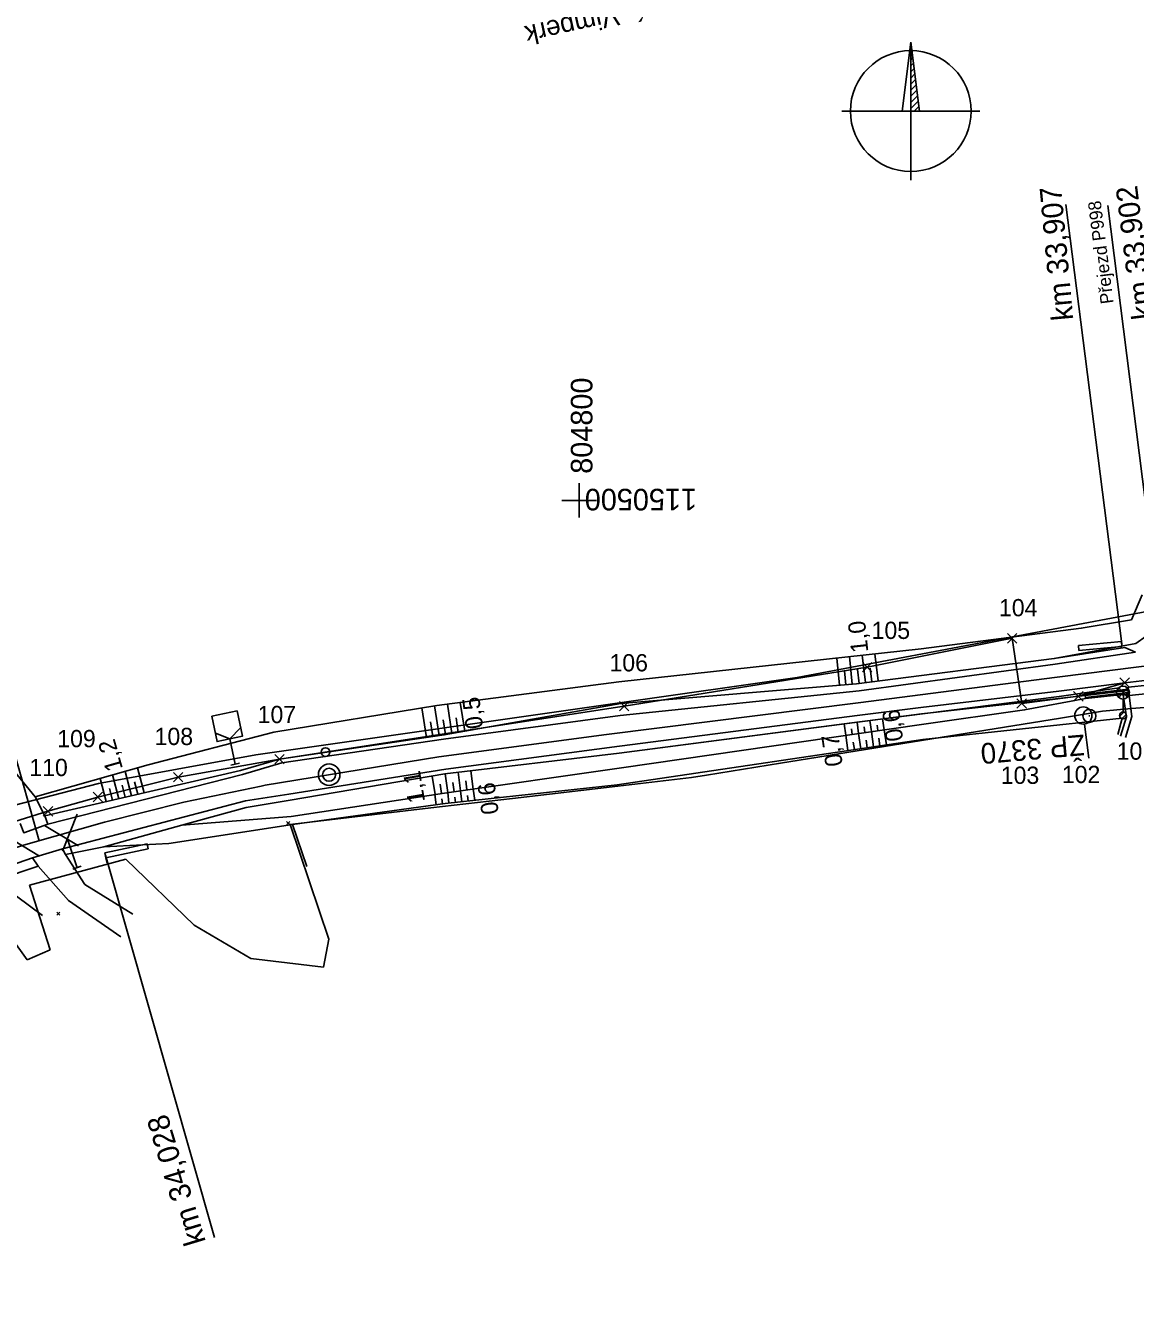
# Model space of a CAD drawing. Extents: x -805730 to -804640, y -1150889 to -1150366.
# Drawn here: x -804864.2 to -804735.5, y -1150592.5 to -1150444.9 of the extents above; entities that cross this region are included whole.
import ezdxf

# ---------------------------------------------------------------- set-up
doc = ezdxf.new("R2010")
doc.units = 0
for name, color, linetype in [('0381KM032-037P - Vrstva 1', 7, 'Continuous'), ('0381KM032-037P - Vrstva 13', 7, 'Continuous'), ('0381KM032-037P - Vrstva 17', 7, 'Continuous'), ('0381KM032-037P - Vrstva 25', 7, 'Continuous'), ('0381KM032-037P - Vrstva 36', 7, 'Continuous'), ('0381KM032-037P - Vrstva 4', 7, 'Continuous'), ('0381KM032-037P - Vrstva 43', 7, 'Continuous'), ('0381KM032-037P - Vrstva 48', 7, 'Continuous'), ('0381KM032-037P - Vrstva 49', 7, 'Continuous'), ('0381KM032-037P - Vrstva 51', 7, 'Continuous'), ('0381KM032-037P - Vrstva 7', 7, 'Continuous'), ('0381KM032-037P - Vrstva 9', 7, 'Continuous'), ('Default', 7, 'Continuous'), ('formát', 7, 'Continuous'), ('hran DP - hran DP', 7, 'Continuous'), ('krizky_1000 - souradnice', 7, 'Continuous'), ('krizky_1000 - Vrstva 1', 7, 'Continuous'), ('legenda - Vrstva 7', 7, 'Continuous'), ('PSR_C2_2_Lomove_body_Vimperk - Vrstva 60', 7, 'Continuous'), ('PSR_C2_2_trasa_Vimperk - Kabelová trasa', 7, 'Continuous'), ('vyt_sit - stávající', 7, 'Continuous')]:
    doc.layers.add(name, color=color, linetype=linetype)

msp = doc.modelspace()

# ---------------------------------------------------------------- linework, layer by layer
at = {"layer": '0381KM032-037P - Vrstva 1'}
for points in [[(-804673.35, -1150511.49), (-804675.7, -1150511.78), (-804698.85, -1150514.71), (-804701.61, -1150515.06), (-804722.18, -1150517.67), (-804729.05, -1150518.54), (-804735.1, -1150519.31), (-804744.56, -1150520.5), (-804767.65, -1150523.46), (-804791, -1150526.42)], [(-804791, -1150526.42), (-804796.82, -1150527.16), (-804816.26, -1150529.72), (-804836.43, -1150533.03), (-804836.89, -1150533.13)], [(-804836.89, -1150533.13), (-804845.84, -1150535.01), (-804855.06, -1150537.3), (-804860.78, -1150538.93), (-804864.46, -1150539.98), (-804872.35, -1150542.54)]]:
    msp.add_lwpolyline(points, dxfattribs=at)
at = {"layer": '0381KM032-037P - Vrstva 13'}
msp.add_line((-804736.93, -1150522.56), (-804736.22, -1150522.62), dxfattribs=at)
for points in [[(-804736.32, -1150521.88), (-804741.33, -1150522.48), (-804741.32, -1150522.62), (-804736.39, -1150522.04)], [(-804736.33, -1150522.27), (-804741.29, -1150522.87), (-804741.32, -1150522.62)], [(-804741.29, -1150522.87), (-804741.28, -1150522.98), (-804736.24, -1150522.43)], [(-804736.93, -1150522.56), (-804736.54, -1150525.1), (-804737.22, -1150527.34)], [(-804736.32, -1150521.88), (-804736.39, -1150522.04), (-804736.33, -1150522.27), (-804736.24, -1150522.43)], [(-804736.22, -1150522.62), (-804735.92, -1150525.05), (-804736.64, -1150527.49)]]:
    msp.add_lwpolyline(points, dxfattribs=at)
at = {"layer": '0381KM032-037P - Vrstva 17'}
msp.add_line((-804831.6, -1150542.45), (-804833.23, -1150537.58), dxfattribs=at)
for points in [[(-804734.71, -1150510.96), (-804735.96, -1150513.84), (-804741.77, -1150514.83), (-804760.36, -1150517.2), (-804795.4, -1150521.06), (-804816.51, -1150523.78), (-804835.4, -1150526.88), (-804850, -1150530.66), (-804863.08, -1150534.36), (-804866.23, -1150530.55), (-804868.05, -1150528.28)], [(-804833.23, -1150537.58), (-804815.54, -1150535.16), (-804795.6, -1150532.98), (-804760.14, -1150527.72), (-804737.02, -1150525.24), (-804737.52, -1150527.15)]]:
    msp.add_lwpolyline(points, dxfattribs=at)
at = {"layer": '0381KM032-037P - Vrstva 25'}
for p, q in [((-804737.43, -1150521.73), (-804736.43, -1150522.84)), ((-804737.41, -1150522.86), (-804736.43, -1150521.74)), ((-804736.93, -1150523.04), (-804736.93, -1150524.54)), ((-804737.32, -1150525.02), (-804736.85, -1150524.55)), ((-804737.06, -1150525.32), (-804736.56, -1150524.82))]:
    msp.add_line(p, q, dxfattribs=at)
for centre, radius in [((-804736.94, -1150522.29), 0.749), ((-804736.93, -1150524.94), 0.4), ((-804736.93, -1150524.94), 0.4)]:
    msp.add_circle(centre, radius, dxfattribs=at)
at = {"layer": '0381KM032-037P - Vrstva 36'}
for p, q in [((-804741.54, -1150524.95), (-804741.54, -1150524.95)), ((-804741.41, -1150525.95), (-804740.91, -1150529.91))]:
    msp.add_line(p, q, dxfattribs=at)
msp.add_circle((-804741.54, -1150524.95), 1, dxfattribs=at)
at = {"layer": '0381KM032-037P - Vrstva 4'}
for p, q in [((-804738.68, -1150465.82), (-804731.99, -1150518.9)), ((-804874.8, -1150496.75), (-804862.62, -1150539.46)), ((-804859.94, -1150540.68), (-804858.22, -1150536.4)), ((-804862.01, -1150537.68), (-804858.05, -1150540.04)), ((-804862.58, -1150541.24), (-804866.52, -1150538.84)), ((-804858.24, -1150542.59), (-804859.36, -1150539.27)), ((-804854.94, -1150541.15), (-804854.94, -1150541.15)), ((-804858.72, -1150542.75), (-804857.77, -1150542.43))]:
    msp.add_line(p, q, dxfattribs=at)
for points in [[(-804735.49, -1150517.59), (-804736.73, -1150517.05), (-804744.9, -1150518.34), (-804767.83, -1150521.26)], [(-804735.49, -1150517.59), (-804744.82, -1150519), (-804767.55, -1150522.1)], [(-804767.83, -1150521.26), (-804795.17, -1150523.55), (-804815.65, -1150527.19), (-804834.76, -1150530), (-804839.27, -1150531.31), (-804861.98, -1150536.58), (-804861.64, -1150537.54)], [(-804767.55, -1150522.1), (-804795.24, -1150524.96), (-804815.73, -1150527.69), (-804834.48, -1150530.44), (-804839.03, -1150531.78), (-804861.64, -1150537.54)], [(-804736.74, -1150521.15), (-804737.38, -1150521.73), (-804744.34, -1150522.73), (-804767.48, -1150525.67)], [(-804736.74, -1150521.15), (-804744.39, -1150522.13), (-804760.4, -1150524), (-804767.46, -1150524.91)], [(-804767.46, -1150524.91), (-804795.31, -1150528.51), (-804815.46, -1150531.15), (-804833.67, -1150534.06), (-804838.71, -1150534.85), (-804859.92, -1150540.42), (-804859.57, -1150541.07)], [(-804767.48, -1150525.67), (-804795.35, -1150529.3), (-804815.58, -1150531.71), (-804833.51, -1150534.75), (-804838.64, -1150535.6), (-804846.07, -1150537.67)], [(-804859.57, -1150541.07), (-804855.14, -1150540.16), (-804846.07, -1150537.67)], [(-804862.73, -1150542.41), (-804863.39, -1150541.46), (-804892.29, -1150551.48), (-804910.22, -1150558.86), (-804951.61, -1150576.23), (-804993.7, -1150593.96), (-805038.63, -1150612.92), (-805049.62, -1150617.53), (-805055.59, -1150619.94), (-805066.74, -1150624.75), (-805096.44, -1150637.01)], [(-804864.94, -1150543.15), (-804862.73, -1150542.41), (-804862.73, -1150542.41)]]:
    msp.add_lwpolyline(points, dxfattribs=at)
at = {"layer": '0381KM032-037P - Vrstva 43'}
msp.add_lwpolyline([(-804736.33, -1150521.65), (-804729.5, -1150520.98), (-804729.45, -1150521.92), (-804736.22, -1150522.62)], close=True, dxfattribs=at)
at = {"layer": '0381KM032-037P - Vrstva 48'}
for p, q in [((-804768.33, -1150521.3), (-804768.64, -1150518.12)), ((-804766.81, -1150521.13), (-804767.19, -1150517.96)), ((-804765.32, -1150520.94), (-804765.7, -1150517.79)), ((-804769.83, -1150521.43), (-804770.13, -1150518.28)), ((-804767.55, -1150521.23), (-804767.74, -1150519.63)), ((-804766.07, -1150521.04), (-804766.25, -1150519.46)), ((-804769.08, -1150521.37), (-804769.23, -1150519.78)), ((-804817.72, -1150527.49), (-804818.25, -1150524.06)), ((-804816.23, -1150527.27), (-804816.77, -1150523.82)), ((-804814.76, -1150527.03), (-804815.28, -1150523.62)), ((-804813.28, -1150526.77), (-804813.79, -1150523.43)), ((-804815.5, -1150527.16), (-804815.76, -1150525.44)), ((-804814.02, -1150526.9), (-804814.28, -1150525.21)), ((-804766.12, -1150526.81), (-804766.3, -1150525.53)), ((-804764.64, -1150526.59), (-804764.81, -1150525.34)), ((-804816.97, -1150527.38), (-804817.24, -1150525.66)), ((-804769.09, -1150527.24), (-804769.27, -1150525.92)), ((-804768.35, -1150527.13), (-804768.44, -1150526.48)), ((-804767.6, -1150527.03), (-804767.78, -1150525.73)), ((-804766.86, -1150526.92), (-804766.95, -1150526.27)), ((-804765.87, -1150528.57), (-804766.12, -1150526.81)), ((-804765.38, -1150526.7), (-804765.46, -1150526.07)), ((-804764.38, -1150528.35), (-804764.64, -1150526.59)), ((-804768.83, -1150529.01), (-804769.09, -1150527.24)), ((-804768.09, -1150528.9), (-804768.22, -1150528.02)), ((-804767.35, -1150528.79), (-804767.61, -1150527.03)), ((-804766.61, -1150528.68), (-804766.74, -1150527.8)), ((-804765.12, -1150528.46), (-804765.25, -1150527.58)), ((-804851.93, -1150534.25), (-804852.66, -1150531.42)), ((-804850.47, -1150533.91), (-804851.22, -1150531.01)), ((-804812.28, -1150533.47), (-804812.56, -1150531.35)), ((-804854.85, -1150534.93), (-804855.55, -1150532.23)), ((-804853.39, -1150534.59), (-804854.11, -1150531.82)), ((-804851.2, -1150534.08), (-804851.57, -1150532.65)), ((-804816.7, -1150534.11), (-804817.05, -1150531.96)), ((-804815.96, -1150534), (-804816.14, -1150532.92)), ((-804815.25, -1150533.89), (-804815.54, -1150531.71)), ((-804814.51, -1150533.79), (-804814.65, -1150532.7)), ((-804813.77, -1150533.68), (-804814.05, -1150531.53)), ((-804813.02, -1150533.57), (-804813.16, -1150532.51)), ((-804854.12, -1150534.76), (-804854.48, -1150533.4)), ((-804852.66, -1150534.42), (-804853.02, -1150533.02)), ((-804816.58, -1150535.3), (-804816.73, -1150534.11)), ((-804815.1, -1150535.11), (-804815.25, -1150533.89)), ((-804813.6, -1150534.95), (-804813.76, -1150533.68)), ((-804812.86, -1150534.87), (-804812.94, -1150534.22)), ((-804812.11, -1150534.78), (-804812.28, -1150533.47)), ((-804815.84, -1150535.2), (-804815.92, -1150534.6)), ((-804814.35, -1150535.03), (-804814.43, -1150534.41))]:
    msp.add_line(p, q, dxfattribs=at)
at = {"layer": '0381KM032-037P - Vrstva 49'}
for p, q in [((-804861.98, -1150536.58), (-804863.08, -1150534.36)), ((-804833.93, -1150537.24), (-804833.57, -1150537.6)), ((-804833.57, -1150537.24), (-804833.92, -1150537.6)), ((-804855.14, -1150540.16), (-804859.57, -1150541.07)), ((-804860.23, -1150547.75), (-804860.58, -1150548.11)), ((-804860.58, -1150547.76), (-804860.23, -1150548.11))]:
    msp.add_line(p, q, dxfattribs=at)
for points in [[(-804731.33, -1150510.42), (-804733.06, -1150514.89), (-804735.43, -1150516.61), (-804744.9, -1150518.34), (-804767.83, -1150521.26), (-804795.17, -1150523.55), (-804815.65, -1150527.19), (-804834.76, -1150530), (-804839.27, -1150531.31), (-804861.98, -1150536.58)], [(-804735.96, -1150513.84), (-804741.77, -1150514.83), (-804760.36, -1150517.2), (-804795.4, -1150521.06), (-804816.51, -1150523.78), (-804835.4, -1150526.88), (-804850, -1150530.66), (-804863.08, -1150534.36)], [(-804741.32, -1150522.62), (-804760.31, -1150524.76), (-804795.35, -1150529.3), (-804815.58, -1150531.71), (-804833.51, -1150534.75), (-804838.64, -1150535.6), (-804846.07, -1150537.67)], [(-804846.07, -1150537.67), (-804833.4, -1150536.66), (-804815.63, -1150533.95), (-804795.08, -1150531.02), (-804760.31, -1150525.97), (-804748.35, -1150524.3), (-804741.28, -1150522.98)], [(-804741.32, -1150522.62), (-804741.29, -1150522.87), (-804741.28, -1150522.98)], [(-804737.02, -1150525.24), (-804760.14, -1150527.72), (-804795.6, -1150532.98), (-804815.54, -1150535.16), (-804833.23, -1150537.58)], [(-804833.23, -1150537.58), (-804847.59, -1150539.77), (-804855.14, -1150540.16)], [(-804859.57, -1150541.07), (-804857.34, -1150544.52), (-804851.77, -1150547.99)], [(-804869.27, -1150544.65), (-804865.03, -1150543.19), (-804864.94, -1150543.15), (-804862.73, -1150542.41)], [(-804862.73, -1150542.41), (-804859.23, -1150546.38), (-804853.15, -1150550.59)], [(-804865.78, -1150545.2), (-804865.26, -1150545.89), (-804862.25, -1150548.13)]]:
    msp.add_lwpolyline(points, dxfattribs=at)
at = {"layer": '0381KM032-037P - Vrstva 51'}
msp.add_line((-804861.98, -1150536.58), (-804863.08, -1150534.36), dxfattribs=at)
for points in [[(-804736.22, -1150522.62), (-804735.92, -1150525.05), (-804736.64, -1150527.49)], [(-804861.98, -1150536.58), (-804861.64, -1150537.54), (-804864.42, -1150538.53), (-804864.84, -1150537.45)], [(-804859.57, -1150541.07), (-804859.92, -1150540.42), (-804863.39, -1150541.46), (-804862.73, -1150542.41)], [(-804859.57, -1150541.07), (-804857.34, -1150544.52), (-804851.77, -1150547.99)], [(-804853.15, -1150550.59), (-804859.23, -1150546.38), (-804862.73, -1150542.41)]]:
    msp.add_lwpolyline(points, dxfattribs=at)
at = {"layer": '0381KM032-037P - Vrstva 7'}
for p, q in [((-804840.52, -1150527.66), (-804839.9, -1150530.59)), ((-804829.48, -1150529.18), (-804829.38, -1150529.18)), ((-804840.39, -1150530.7), (-804839.41, -1150530.49))]:
    msp.add_line(p, q, dxfattribs=at)
for points in [[(-804840.52, -1150527.66), (-804839.05, -1150527.35), (-804839.67, -1150524.41), (-804842.6, -1150525.03), (-804841.99, -1150527.97), (-804840.52, -1150527.66)], [(-804842.19, -1150526.99), (-804840.52, -1150527.66), (-804839.26, -1150526.37)]]:
    msp.add_lwpolyline(points, dxfattribs=at)
for centre, radius in [((-804829.43, -1150529.18), 0.5), ((-804829, -1150531.81), 1.25), ((-804829, -1150531.81), 0.752)]:
    msp.add_circle(centre, radius, dxfattribs=at)
at = {"layer": '0381KM032-037P - Vrstva 9'}
for p, q in [((-804737.08, -1150516.65), (-804743.56, -1150465.71)), ((-804737.11, -1150516.35), (-804742.09, -1150516.81)), ((-804737.11, -1150516.35), (-804737.17, -1150515.76)), ((-804737.06, -1150516.95), (-804737.11, -1150516.35)), ((-804742.09, -1150516.81), (-804742.04, -1150517.41)), ((-804742.04, -1150517.41), (-804737.06, -1150516.95)), ((-804850.11, -1150539.83), (-804855, -1150540.85)), ((-804849.98, -1150540.42), (-804850.11, -1150539.83)), ((-804855, -1150540.85), (-804854.88, -1150541.44)), ((-804854.94, -1150541.15), (-804842.3, -1150585.48)), ((-804854.88, -1150541.44), (-804849.98, -1150540.42)), ((-804854.88, -1150541.44), (-804854.75, -1150542.03))]:
    msp.add_line(p, q, dxfattribs=at)
at = {"layer": 'formát'}
for p, q in [((-804761.55, -1150446.86), (-804761.55, -1150462.86)), ((-804761.55, -1150447.49), (-804761.48, -1150447.42)), ((-804761.55, -1150448.2), (-804761.41, -1150448.05)), ((-804761.55, -1150448.91), (-804761.33, -1150448.68)), ((-804761.55, -1150449.61), (-804761.25, -1150449.31)), ((-804761.55, -1150450.32), (-804761.17, -1150449.94)), ((-804761.55, -1150451.03), (-804761.09, -1150450.56)), ((-804761.55, -1150451.74), (-804761.01, -1150451.19)), ((-804761.55, -1150452.44), (-804760.93, -1150451.82)), ((-804761.55, -1150453.15), (-804760.86, -1150452.45)), ((-804761.55, -1150453.86), (-804760.78, -1150453.08)), ((-804761.55, -1150454.56), (-804760.7, -1150453.71)), ((-804761.14, -1150454.86), (-804760.62, -1150454.34)), ((-804769.55, -1150454.86), (-804753.55, -1150454.86))]:
    msp.add_line(p, q, dxfattribs=at)
for points in [[(-804761.55, -1150446.86), (-804762.55, -1150454.86)], [(-804761.55, -1150446.86), (-804760.55, -1150454.86)], [(-804761.55, -1150446.86), (-804761.55, -1150454.86), (-804760.55, -1150454.86), (-804761.55, -1150446.86)]]:
    msp.add_lwpolyline(points, dxfattribs=at)
msp.add_circle((-804761.55, -1150454.86), 7, dxfattribs=at)
at = {"layer": 'hran DP - hran DP'}
for p, q in [((-804747.72, -1150515.43), (-804723.03, -1150510.78)), ((-804774.72, -1150520.52), (-804747.72, -1150515.43)), ((-804795.05, -1150523.42), (-804774.72, -1150520.52)), ((-804837.49, -1150529.49), (-804795.05, -1150523.42)), ((-804729.97, -1150523.63), (-804736.36, -1150524.18)), ((-804744.2, -1150525.25), (-804766.8, -1150528.89)), ((-804739.31, -1150524.46), (-804744.2, -1150525.25)), ((-804736.36, -1150524.18), (-804739.31, -1150524.46)), ((-804855.75, -1150532.82), (-804837.49, -1150529.49)), ((-804766.8, -1150528.89), (-804776.65, -1150530.47)), ((-804776.65, -1150530.47), (-804785.22, -1150531.85)), ((-804868.93, -1150536.25), (-804855.75, -1150532.82)), ((-804786.96, -1150532.13), (-804795.52, -1150533.13)), ((-804785.22, -1150531.85), (-804786.96, -1150532.13)), ((-804795.52, -1150533.13), (-804807.75, -1150534.56)), ((-804817.19, -1150535.66), (-804833.21, -1150537.53)), ((-804807.75, -1150534.56), (-804817.19, -1150535.66)), ((-804833.21, -1150537.53), (-804833.52, -1150537.57)), ((-804833.52, -1150537.57), (-804829.05, -1150550.88)), ((-804852.58, -1150541.61), (-804863.76, -1150544.6)), ((-804844.64, -1150549.24), (-804852.58, -1150541.61)), ((-804863.76, -1150544.6), (-804861.34, -1150552.12)), ((-804864.02, -1150553.26), (-804868.47, -1150547.08)), ((-804838.07, -1150553.11), (-804844.64, -1150549.24)), ((-804829.05, -1150550.88), (-804829.67, -1150554.12)), ((-804861.34, -1150552.12), (-804864.02, -1150553.26)), ((-804829.67, -1150554.12), (-804838.07, -1150553.11))]:
    msp.add_line(p, q, dxfattribs=at)
at = {"layer": 'krizky_1000 - Vrstva 1'}
for points in [[(-804800, -1150498), (-804800, -1150502)], [(-804802, -1150500), (-804798, -1150500)]]:
    msp.add_lwpolyline(points, dxfattribs=at)
at = {"layer": 'PSR_C2_2_Lomove_body_Vimperk - Vrstva 60'}
for p, q in [((-804750.33, -1150516.54), (-804749.23, -1150515.44)), ((-804749.23, -1150516.54), (-804750.33, -1150515.44)), ((-804767.15, -1150519.9), (-804766.05, -1150518.8)), ((-804766.05, -1150519.9), (-804767.15, -1150518.8)), ((-804737.29, -1150521.7), (-804736.19, -1150520.59)), ((-804736.19, -1150521.7), (-804737.29, -1150520.59)), ((-804742.67, -1150523.27), (-804741.57, -1150522.17)), ((-804741.57, -1150523.27), (-804742.67, -1150522.17)), ((-804795.34, -1150524.41), (-804794.24, -1150523.31)), ((-804794.24, -1150524.41), (-804795.34, -1150523.31)), ((-804749.23, -1150524.1), (-804748.13, -1150523)), ((-804748.13, -1150524.1), (-804749.23, -1150523)), ((-804835.31, -1150530.55), (-804834.21, -1150529.45)), ((-804834.21, -1150530.55), (-804835.31, -1150529.45)), ((-804847.06, -1150532.64), (-804845.96, -1150531.54)), ((-804845.96, -1150532.64), (-804847.06, -1150531.54)), ((-804856.38, -1150534.95), (-804855.28, -1150533.85)), ((-804855.28, -1150534.95), (-804856.38, -1150533.85)), ((-804862.16, -1150536.6), (-804861.06, -1150535.5)), ((-804861.06, -1150536.6), (-804862.16, -1150535.5))]:
    msp.add_line(p, q, dxfattribs=at)
at = {"layer": 'PSR_C2_2_trasa_Vimperk - Kabelová trasa'}
for p, q in [((-804749.78, -1150515.99), (-804766.6, -1150519.35)), ((-804749.78, -1150515.99), (-804748.68, -1150523.55)), ((-804728.64, -1150520.2), (-804736.74, -1150521.15)), ((-804736.74, -1150521.15), (-804742.12, -1150522.72)), ((-804742.12, -1150522.72), (-804748.68, -1150523.55)), ((-804846.51, -1150532.09), (-804855.83, -1150534.4)), ((-804855.83, -1150534.4), (-804861.61, -1150536.05))]:
    msp.add_line(p, q, dxfattribs=at)
for points in [[(-804766.6, -1150519.35), (-804794.79, -1150523.86), (-804834.76, -1150530), (-804846.51, -1150532.09)], [(-804861.61, -1150536.05), (-804874.49, -1150540.07), (-804895.8, -1150547.79), (-804932.46, -1150563.38), (-804958.05, -1150574.66), (-804991.35, -1150588.71)]]:
    msp.add_lwpolyline(points, dxfattribs=at)
at = {"layer": 'vyt_sit - stávající'}
msp.add_line((-804740.89, -1150524.99), (-804740.79, -1150524.99), dxfattribs=at)
msp.add_circle((-804740.83, -1150524.99), 0.756, dxfattribs=at)

# ---------------------------------------------------------------- texts
at = {"layer": '0381KM032-037P - Vrstva 4'}
for s, height, p in [('km 33,902', 2.5, (-804733.36, -1150478.88)), ('Přejezd P998', 1.5, (-804738.02, -1150477.13))]:
    msp.add_text(s, height=height, rotation=97.1938, dxfattribs=at).set_placement(p)
at = {"layer": '0381KM032-037P - Vrstva 48'}
for s, rotation, p in [('1,0', 96.2855, (-804766.46, -1150517.56)), ('0,5', 97.3237, (-804811.13, -1150526.38)), ('0,6', 97.4164, (-804762.42, -1150527.82)), ('1,2', 105.8168, (-804852.9, -1150531.1)), ('0,7', 98.2601, (-804769.42, -1150530.71)), ('1,1', 99.611, (-804817.86, -1150534.9)), ('0,6', 98.12, (-804809.31, -1150536.28))]:
    msp.add_text(s, height=2, rotation=rotation, dxfattribs=at).set_placement(p)
at = {"layer": '0381KM032-037P - Vrstva 9'}
for s, rotation, p in [('km 33,907', 95.2837, (-804742.69, -1150479.05)), ('km 34,028', 106.8099, (-804843.28, -1150585.95))]:
    msp.add_text(s, height=2.5, rotation=rotation, dxfattribs=at).set_placement(p)
at = {"layer": 'Default'}
for s, p in [('104', (-804751.32, -1150513.44)), ('105', (-804766.09, -1150516.07)), ('106', (-804796.49, -1150519.83)), ('107', (-804837.29, -1150525.83)), ('109', (-804860.53, -1150528.62)), ('108', (-804849.24, -1150528.37)), ('101', (-804737.67, -1150530.07)), ('110', (-804863.77, -1150531.97)), ('103', (-804751.11, -1150532.87)), ('102', (-804744.03, -1150532.78))]:
    msp.add_text(s, height=2, dxfattribs=at).set_placement(p)
at = {"layer": 'krizky_1000 - souradnice'}
for s, rotation, p in [('804800', 90, (-804798.47, -1150496.92)), ('1150500', 180, (-804786.34, -1150498.66))]:
    msp.add_text(s, height=2.5, rotation=rotation, dxfattribs=at).set_placement(p)
at = {"layer": 'legenda - Vrstva 7'}
msp.add_text('k.ú. Vimperk', height=2.25, rotation=192.4227, dxfattribs=at).set_placement((-804790.13, -1150441.44))
at = {"layer": 'vyt_sit - stávající'}
msp.add_text('ŽP 3370', height=2.4, rotation=185, dxfattribs=at).set_placement((-804741.45, -1150527.14))

doc.saveas('drawing.dxf')
